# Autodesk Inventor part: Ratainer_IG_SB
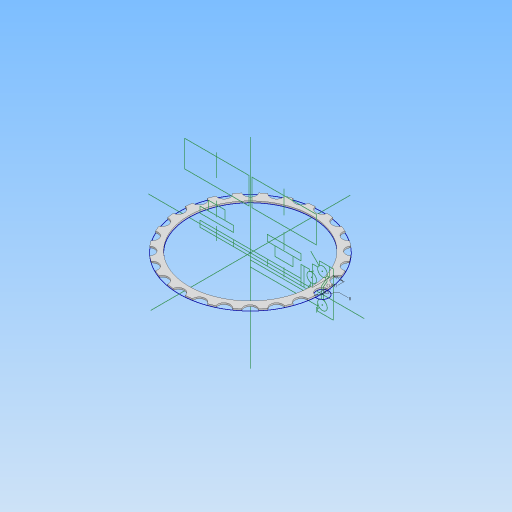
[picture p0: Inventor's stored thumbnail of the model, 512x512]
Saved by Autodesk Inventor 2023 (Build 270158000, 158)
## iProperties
Created: 2024-05
Part Number: Ratainer_IG_SB
Material: 一般
Document SubType Name: Modeling
Designer: kumagai
Density: 1 g/cm^3
Appearance: 既定
Author: kumagai
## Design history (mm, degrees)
derived "CoreSketch.ipt"
  sketch "Vertical"
    geometry: L1 (0, 65.337)-(0, -65.337) reference; L2 (-46.2, 0)-(46.2, 0) reference; L3 (-11, 2)-(11, 2) reference; L4 (11, 2)-(11, -2) reference; L5 (11, -2)-(-11, -2) reference; L6 (-11, -2)-(-11, 2) reference; L7 (11, 2)-(33, 2) reference; L8 (33, 2)-(33, -2) reference; L9 (33, -2)-(11, -2) reference; L10 (11, -2)-(11, 2) reference; L11 (22, 2.772)-(22, -2.683) reference; L12 (-33, 2)-(-11, 2) reference; L13 (-11, 2)-(-11, -2) reference; L14 (-11, -2)-(-33, -2) reference; L15 (-33, -2)-(-33, 2) reference; L16 (-22, 4.087)-(-22, -4.199) reference; L17 (-33, 10)-(-11, 10) reference; L18 (-11, 10)-(-11, 6) reference; L19 (-11, 6)-(-33, 6) reference; L20 (-33, 6)-(-33, 10) reference; L21 (-27.353, 10)-(-16.647, 10) reference; L22 (-16.647, 10)-(-16.647, 16) reference; L23 (-16.647, 16)-(-27.353, 16) reference; L24 (-27.353, 16)-(-27.353, 10) reference; L25 (11, 16)-(33, 16) reference; L26 (33, 16)-(33, 12) reference; L27 (33, 12)-(11, 12) reference; L28 (11, 12)-(11, 16) reference; L29 (16.134, 12)-(27.866, 12) reference; L30 (27.866, 12)-(27.866, 6) reference; L31 (27.866, 6)-(16.134, 6) reference; L32 (16.134, 6)-(16.134, 12) reference; L33 (-22, 18.272)-(-22, 9.031) reference; L34 (22, 22.635)-(22, 12.71) reference; L35 (33, -2)-(35, -2) reference; L36 (35, -2)-(35, 10) reference; L37 (35, 10)-(33, 10) reference; L38 (33, 10)-(33, -2) reference; L39 (0, -4)-(37.5, -4) reference; L40 (40.5, -1)-(40.5, 14) reference; L41 (43.9, -8)-(0, -8) reference; L42 (0, -4)-(0, -8) reference; L43 (35, -2)-(39, -2) reference; L44 (39, -2)-(39, 3.066) reference; L45 (38.45, 8.685)-(41.471, 10.429) reference; L46 (38.45, 10)-(35, 10) reference; L47 (40.5, 9.291)-(41.55, 8.685) reference; L48 (41.55, 3.315)-(40.5, 2.709) reference; L49 (37.5, -4)-(40.5, -1) reference; L50 (-43, 43.294)-(-1, 43.294) reference; L51 (-1, 43.294)-(-1, 26) reference; L52 (-1, 26)-(-43, 26) reference; L53 (-43, 26)-(-43, 43.294) reference; L54 (1, 43.294)-(43, 43.294) reference; L55 (43, 43.294)-(43, 26) reference; L56 (43, 26)-(1, 26) reference; L57 (1, 26)-(1, 43.294) reference; L58 (-22, 45.556)-(-22, 31.232) reference; L59 (22, 47.214)-(22, 32.287) reference; L60 (47.5, 4.402)-(47.5, -2.116) reference; L61 (43.6, -11)-(54, -11) reference; L62 (54, -11)-(54, 18) reference; L63 (45.45, -3.315)-(46.5, -2.709) reference; L64 (47.5, -2.116)-(49.192, -3.808) reference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; A1 r 3.1 centre (40, 6) between (39, 3.066) and (38.45, 8.685) reference; A2 r 3.1 centre (47, -6) between (45.45, -3.315) and (49.192, -3.808) reference; A3 r 3.1 centre (47, 13) between (43.9, 13) and (49, 10.631) reference; 2 further points; 1 other entity
    constraints: 1 other
sketch "スケッチ3"
  geometry: L1 (0, -65.1)-(0, 65.1) reference; L2 (-74.1, 0)-(66.6, 0) reference; C1 r 4 at (-47, 0); 7 further points
  constraints: 3 coincident, 2 horizontal alignment, 2 point on line, 1 centre point, 4 other
  dimensions: "d28" = 1.96961 distance of point (-45.03, 0) point (-47, 0) (derived); "d29" = 8 diameter of C1; "d31" = 7 distance of C1.centre point (-40, 0); "d39" = 0.5 distance of point (-46.5, 0) point (-47, 0)
extrude "押し出し4" new body sketch "スケッチ3" distance "d32" = 1; taper "d33" = 0 deg
extrude "押し出し5" cut sketch "スケッチ3" extent not by distance; stored distance "d34" = 0; taper "d35" = 0 deg
node "ソリッド2"
pattern_circular "円形状パターン2" dims angle "d37" = 360 deg
